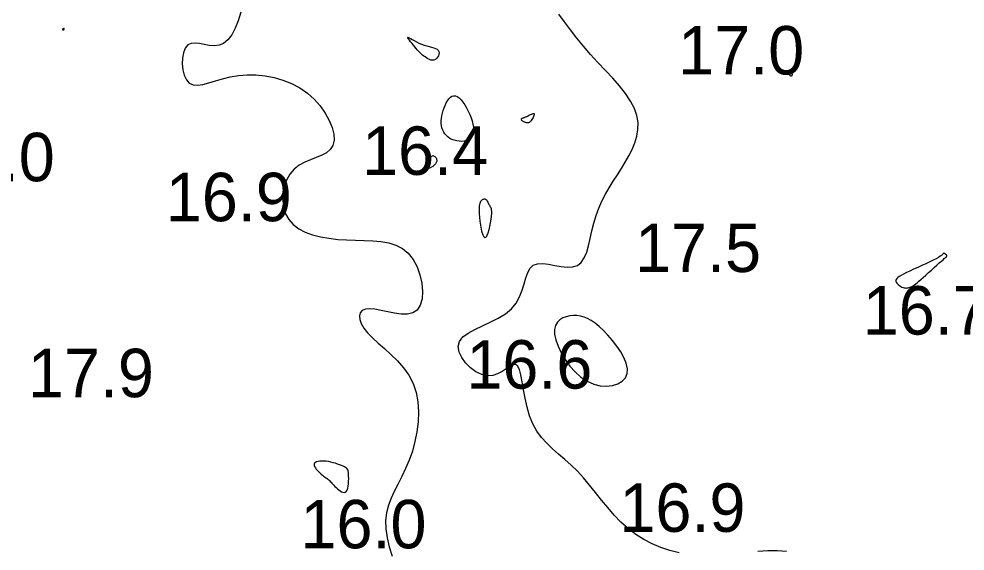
# Model space of a CAD drawing. Extents: x 3040093 to 3056816, y 408076 to 509144.
# Drawn here: x 3045378.4 to 3045476.1, y 433880.3 to 433935.3 of the extents above; entities that cross this region are included whole.
import ezdxf

# ---------------------------------------------------------------- set-up
doc = ezdxf.new("R2010")
doc.units = 0
doc.layers.add('V-CHAN-CONT-EL17', color=7, linetype='Continuous')
doc.layers.add('V-TOPO-SOUN-0610', color=7, linetype='Continuous')

msp = doc.modelspace()

# ---------------------------------------------------------------- linework, layer by layer
at = {"layer": 'V-CHAN-CONT-EL17'}
for points in [[(3045401.338, 433935.95), (3045401.071, 433935.083), (3045400.759, 433934.303), (3045400.404, 433933.637), (3045400.007, 433933.107), (3045399.568, 433932.74), (3045399.09, 433932.546), (3045398.587, 433932.493), (3045398.072, 433932.535), (3045397.562, 433932.627), (3045397.071, 433932.722), (3045396.615, 433932.775), (3045396.208, 433932.74), (3045395.866, 433932.573), (3045395.601, 433932.242), (3045395.416, 433931.776), (3045395.312, 433931.221), (3045395.29, 433930.619), (3045395.349, 433930.017), (3045395.49, 433929.456), (3045395.714, 433928.983), (3045396.021, 433928.642), (3045396.411, 433928.463), (3045396.88, 433928.428), (3045397.424, 433928.504), (3045398.037, 433928.659), (3045398.716, 433928.861), (3045399.454, 433929.079), (3045400.249, 433929.279), (3045401.094, 433929.43), (3045401.984, 433929.504), (3045402.904, 433929.495), (3045403.84, 433929.402), (3045404.776, 433929.222), (3045405.696, 433928.955), (3045406.586, 433928.597), (3045407.43, 433928.149), (3045408.212, 433927.608), (3045408.917, 433926.977), (3045409.536, 433926.279), (3045410.058, 433925.541), (3045410.472, 433924.789), (3045410.768, 433924.052), (3045410.937, 433923.356), (3045410.967, 433922.728), (3045410.85, 433922.196), (3045410.581, 433921.776), (3045410.185, 433921.449), (3045409.691, 433921.184), (3045409.132, 433920.952), (3045408.537, 433920.721), (3045407.938, 433920.463), (3045407.365, 433920.147), (3045406.848, 433919.742), (3045406.415, 433919.228), (3045406.075, 433918.623), (3045405.834, 433917.952), (3045405.696, 433917.242), (3045405.668, 433916.519), (3045405.755, 433915.81), (3045405.961, 433915.142), (3045406.294, 433914.54), (3045406.754, 433914.026), (3045407.329, 433913.597), (3045408.001, 433913.248), (3045408.756, 433912.97), (3045409.576, 433912.757), (3045410.445, 433912.601), (3045411.346, 433912.495), (3045412.264, 433912.431), (3045413.181, 433912.401), (3045414.087, 433912.381), (3045414.97, 433912.346), (3045415.818, 433912.271), (3045416.62, 433912.13), (3045417.364, 433911.898), (3045418.039, 433911.55), (3045418.634, 433911.061), (3045419.138, 433910.417), (3045419.544, 433909.654), (3045419.845, 433908.818), (3045420.035, 433907.956), (3045420.108, 433907.115), (3045420.057, 433906.344), (3045419.876, 433905.688), (3045419.559, 433905.194), (3045419.106, 433904.896), (3045418.542, 433904.767), (3045417.9, 433904.769), (3045417.212, 433904.86), (3045416.51, 433905.001), (3045415.827, 433905.153), (3045415.195, 433905.275), (3045414.645, 433905.327), (3045414.206, 433905.279), (3045413.882, 433905.132), (3045413.676, 433904.899), (3045413.587, 433904.591), (3045413.616, 433904.219), (3045413.765, 433903.795), (3045414.033, 433903.331), (3045414.423, 433902.838), (3045414.928, 433902.324), (3045415.523, 433901.785), (3045416.173, 433901.213), (3045416.848, 433900.602), (3045417.513, 433899.943), (3045418.137, 433899.229), (3045418.687, 433898.453), (3045419.13, 433897.607), (3045419.441, 433896.688), (3045419.625, 433895.711), (3045419.693, 433894.694), (3045419.659, 433893.657), (3045419.533, 433892.617), (3045419.328, 433891.596), (3045419.056, 433890.61), (3045418.729, 433889.679), (3045418.361, 433888.817), (3045417.97, 433888.012), (3045417.577, 433887.247), (3045417.202, 433886.506), (3045416.866, 433885.772), (3045416.589, 433885.029), (3045416.391, 433884.259), (3045416.294, 433883.447), (3045416.311, 433882.579), (3045416.439, 433881.666), (3045416.668, 433880.719), (3045416.988, 433879.752)], [(3045446.621, 433880.118), (3045445.66, 433880.351), (3045444.725, 433880.658), (3045443.821, 433881.038), (3045442.952, 433881.492), (3045442.124, 433882.018), (3045441.341, 433882.618), (3045440.604, 433883.288), (3045439.908, 433884.013), (3045439.243, 433884.777), (3045438.603, 433885.56), (3045437.977, 433886.347), (3045437.357, 433887.118), (3045436.735, 433887.856), (3045436.102, 433888.545), (3045435.453, 433889.172), (3045434.798, 433889.752), (3045434.151, 433890.307), (3045433.524, 433890.857), (3045432.932, 433891.424), (3045432.387, 433892.029), (3045431.903, 433892.693), (3045431.494, 433893.437), (3045431.167, 433894.272), (3045430.912, 433895.166), (3045430.71, 433896.077), (3045430.546, 433896.963), (3045430.402, 433897.782), (3045430.262, 433898.492), (3045430.108, 433899.05), (3045429.924, 433899.416), (3045429.696, 433899.561), (3045429.421, 433899.524), (3045429.1, 433899.356), (3045428.733, 433899.11), (3045428.319, 433898.839), (3045427.861, 433898.594), (3045427.357, 433898.428), (3045426.808, 433898.394), (3045426.221, 433898.531), (3045425.626, 433898.819), (3045425.059, 433899.228), (3045424.556, 433899.724), (3045424.155, 433900.276), (3045423.891, 433900.852), (3045423.8, 433901.419), (3045423.92, 433901.946), (3045424.271, 433902.409), (3045424.817, 433902.82), (3045425.506, 433903.198), (3045426.288, 433903.564), (3045427.109, 433903.938), (3045427.919, 433904.34), (3045428.667, 433904.789), (3045429.3, 433905.307), (3045429.782, 433905.904), (3045430.134, 433906.557), (3045430.393, 433907.233), (3045430.594, 433907.9), (3045430.774, 433908.524), (3045430.968, 433909.075), (3045431.213, 433909.519), (3045431.544, 433909.823), (3045431.987, 433909.969), (3045432.524, 433909.986), (3045433.126, 433909.917), (3045433.765, 433909.806), (3045434.411, 433909.696), (3045435.036, 433909.63), (3045435.611, 433909.651), (3045436.108, 433909.803), (3045436.505, 433910.116), (3045436.815, 433910.576), (3045437.06, 433911.157), (3045437.259, 433911.833), (3045437.435, 433912.577), (3045437.607, 433913.363), (3045437.796, 433914.165), (3045438.024, 433914.956), (3045438.305, 433915.716), (3045438.635, 433916.445), (3045439.003, 433917.148), (3045439.399, 433917.83), (3045439.812, 433918.497), (3045440.231, 433919.155), (3045440.647, 433919.808), (3045441.048, 433920.462), (3045441.424, 433921.122), (3045441.759, 433921.79), (3045442.036, 433922.467), (3045442.24, 433923.154), (3045442.355, 433923.852), (3045442.364, 433924.563), (3045442.251, 433925.288), (3045442, 433926.027), (3045441.602, 433926.783), (3045441.076, 433927.553), (3045440.449, 433928.338), (3045439.747, 433929.136), (3045438.997, 433929.947), (3045438.225, 433930.769), (3045437.457, 433931.601), (3045436.721, 433932.444), (3045436.035, 433933.293), (3045435.393, 433934.137), (3045434.779, 433934.961), (3045434.178, 433935.752)], [(3045457.714, 433880.233), (3045456.746, 433880.302), (3045455.755, 433880.304), (3045454.748, 433880.255)]]:
    msp.add_lwpolyline(points, dxfattribs=at)
for points in [[(3045383.043, 433934.136), (3045383.051, 433934.14), (3045383.059, 433934.144), (3045383.065, 433934.15), (3045383.072, 433934.156), (3045383.078, 433934.164), (3045383.083, 433934.172), (3045383.089, 433934.182), (3045383.094, 433934.193), (3045383.099, 433934.204), (3045383.104, 433934.216), (3045383.108, 433934.227), (3045383.11, 433934.238), (3045383.112, 433934.249), (3045383.111, 433934.258), (3045383.109, 433934.265), (3045383.106, 433934.271), (3045383.1, 433934.274), (3045383.093, 433934.276), (3045383.084, 433934.277), (3045383.075, 433934.276), (3045383.064, 433934.275), (3045383.054, 433934.272), (3045383.043, 433934.269), (3045383.032, 433934.265), (3045383.021, 433934.261), (3045383.01, 433934.257), (3045383, 433934.252), (3045382.99, 433934.248), (3045382.981, 433934.243), (3045382.972, 433934.239), (3045382.965, 433934.235), (3045382.958, 433934.232), (3045382.953, 433934.229), (3045382.948, 433934.226), (3045382.944, 433934.222), (3045382.942, 433934.219), (3045382.939, 433934.215), (3045382.938, 433934.21), (3045382.937, 433934.205), (3045382.937, 433934.198), (3045382.938, 433934.19), (3045382.939, 433934.182), (3045382.942, 433934.174), (3045382.945, 433934.166), (3045382.949, 433934.158), (3045382.954, 433934.151), (3045382.961, 433934.145), (3045382.968, 433934.139), (3045382.977, 433934.135), (3045382.986, 433934.132), (3045382.996, 433934.131), (3045383.006, 433934.13), (3045383.016, 433934.13), (3045383.026, 433934.131), (3045383.035, 433934.133)], [(3045419.324, 433932.373), (3045419.177, 433932.546), (3045419.025, 433932.726), (3045418.881, 433932.902), (3045418.753, 433933.065), (3045418.653, 433933.203), (3045418.591, 433933.306), (3045418.578, 433933.363), (3045418.621, 433933.368), (3045418.716, 433933.326), (3045418.856, 433933.248), (3045419.036, 433933.143), (3045419.247, 433933.022), (3045419.483, 433932.893), (3045419.737, 433932.768), (3045420.003, 433932.655), (3045420.273, 433932.562), (3045420.541, 433932.486), (3045420.8, 433932.42), (3045421.044, 433932.358), (3045421.265, 433932.295), (3045421.457, 433932.223), (3045421.613, 433932.138), (3045421.726, 433932.032), (3045421.793, 433931.903), (3045421.814, 433931.756), (3045421.797, 433931.601), (3045421.744, 433931.447), (3045421.663, 433931.302), (3045421.556, 433931.177), (3045421.43, 433931.079), (3045421.289, 433931.018), (3045421.137, 433931), (3045420.98, 433931.02), (3045420.82, 433931.072), (3045420.662, 433931.146), (3045420.509, 433931.237), (3045420.366, 433931.335), (3045420.235, 433931.435), (3045420.121, 433931.528), (3045420.026, 433931.608), (3045419.945, 433931.68), (3045419.874, 433931.747), (3045419.806, 433931.817), (3045419.736, 433931.893), (3045419.659, 433931.982), (3045419.567, 433932.089), (3045419.457, 433932.218)], [(3045458.164, 433929.374), (3045458.184, 433929.373), (3045458.201, 433929.376), (3045458.216, 433929.384), (3045458.23, 433929.394), (3045458.242, 433929.407), (3045458.254, 433929.421), (3045458.266, 433929.435), (3045458.279, 433929.449), (3045458.291, 433929.463), (3045458.302, 433929.476), (3045458.311, 433929.489), (3045458.318, 433929.503), (3045458.32, 433929.516), (3045458.317, 433929.529), (3045458.309, 433929.543), (3045458.294, 433929.557), (3045458.274, 433929.57), (3045458.249, 433929.584), (3045458.22, 433929.596), (3045458.189, 433929.608), (3045458.156, 433929.617), (3045458.123, 433929.625), (3045458.09, 433929.63), (3045458.058, 433929.632), (3045458.029, 433929.631), (3045458.004, 433929.627), (3045457.982, 433929.62), (3045457.965, 433929.609), (3045457.953, 433929.596), (3045457.949, 433929.579), (3045457.952, 433929.559), (3045457.962, 433929.535), (3045457.98, 433929.51), (3045458.002, 433929.483), (3045458.029, 433929.457), (3045458.057, 433929.433), (3045458.087, 433929.411), (3045458.115, 433929.393), (3045458.142, 433929.38)], [(3045425.062, 433922.91), (3045424.874, 433922.784), (3045424.656, 433922.695), (3045424.415, 433922.64), (3045424.159, 433922.618), (3045423.896, 433922.626), (3045423.635, 433922.663), (3045423.384, 433922.726), (3045423.15, 433922.814), (3045422.935, 433922.925), (3045422.741, 433923.057), (3045422.568, 433923.21), (3045422.418, 433923.382), (3045422.291, 433923.572), (3045422.19, 433923.778), (3045422.115, 433923.999), (3045422.066, 433924.234), (3045422.043, 433924.479), (3045422.044, 433924.734), (3045422.067, 433924.996), (3045422.109, 433925.263), (3045422.17, 433925.532), (3045422.247, 433925.801), (3045422.339, 433926.069), (3045422.443, 433926.331), (3045422.56, 433926.581), (3045422.688, 433926.81), (3045422.828, 433927.008), (3045422.979, 433927.168), (3045423.141, 433927.28), (3045423.313, 433927.337), (3045423.496, 433927.329), (3045423.687, 433927.25), (3045423.885, 433927.107), (3045424.084, 433926.909), (3045424.282, 433926.664), (3045424.475, 433926.382), (3045424.659, 433926.072), (3045424.83, 433925.743), (3045424.985, 433925.403), (3045425.119, 433925.061), (3045425.23, 433924.724), (3045425.314, 433924.395), (3045425.368, 433924.082), (3045425.388, 433923.787), (3045425.37, 433923.518), (3045425.312, 433923.279), (3045425.21, 433923.075)], [(3045430.305, 433924.862), (3045430.307, 433924.892), (3045430.321, 433924.921), (3045430.344, 433924.948), (3045430.374, 433924.974), (3045430.409, 433924.998), (3045430.449, 433925.02), (3045430.491, 433925.04), (3045430.535, 433925.059), (3045430.581, 433925.077), (3045430.63, 433925.096), (3045430.684, 433925.116), (3045430.743, 433925.14), (3045430.81, 433925.168), (3045430.885, 433925.202), (3045430.97, 433925.243), (3045431.064, 433925.292), (3045431.165, 433925.344), (3045431.267, 433925.396), (3045431.366, 433925.442), (3045431.457, 433925.478), (3045431.536, 433925.5), (3045431.597, 433925.503), (3045431.636, 433925.482), (3045431.65, 433925.435), (3045431.641, 433925.365), (3045431.613, 433925.278), (3045431.571, 433925.179), (3045431.519, 433925.075), (3045431.46, 433924.971), (3045431.398, 433924.873), (3045431.338, 433924.786), (3045431.283, 433924.714), (3045431.233, 433924.657), (3045431.187, 433924.614), (3045431.144, 433924.581), (3045431.105, 433924.559), (3045431.068, 433924.544), (3045431.033, 433924.534), (3045430.999, 433924.529), (3045430.965, 433924.526), (3045430.931, 433924.526), (3045430.896, 433924.529), (3045430.86, 433924.534), (3045430.821, 433924.542), (3045430.779, 433924.554), (3045430.734, 433924.569), (3045430.685, 433924.589), (3045430.631, 433924.612), (3045430.574, 433924.638), (3045430.518, 433924.667), (3045430.463, 433924.698), (3045430.413, 433924.731), (3045430.37, 433924.764), (3045430.336, 433924.798), (3045430.314, 433924.83)], [(3045420.635, 433920.099), (3045420.643, 433920.14), (3045420.656, 433920.184), (3045420.672, 433920.232), (3045420.692, 433920.285), (3045420.716, 433920.346), (3045420.742, 433920.416), (3045420.77, 433920.495), (3045420.801, 433920.586), (3045420.835, 433920.683), (3045420.872, 433920.782), (3045420.912, 433920.878), (3045420.957, 433920.967), (3045421.006, 433921.042), (3045421.06, 433921.1), (3045421.12, 433921.135), (3045421.185, 433921.145), (3045421.253, 433921.13), (3045421.321, 433921.095), (3045421.387, 433921.043), (3045421.447, 433920.978), (3045421.499, 433920.904), (3045421.54, 433920.824), (3045421.566, 433920.741), (3045421.577, 433920.659), (3045421.572, 433920.579), (3045421.554, 433920.501), (3045421.524, 433920.425), (3045421.483, 433920.351), (3045421.434, 433920.28), (3045421.378, 433920.213), (3045421.316, 433920.149), (3045421.25, 433920.089), (3045421.181, 433920.033), (3045421.112, 433919.983), (3045421.043, 433919.94), (3045420.976, 433919.904), (3045420.913, 433919.876), (3045420.854, 433919.858), (3045420.802, 433919.85), (3045420.758, 433919.852), (3045420.72, 433919.865), (3045420.69, 433919.885), (3045420.666, 433919.912), (3045420.649, 433919.945), (3045420.638, 433919.981), (3045420.632, 433920.02), (3045420.631, 433920.06)], [(3045425.981, 433915.452), (3045425.979, 433915.711), (3045425.99, 433915.924), (3045426.012, 433916.096), (3045426.044, 433916.232), (3045426.085, 433916.341), (3045426.132, 433916.427), (3045426.184, 433916.496), (3045426.24, 433916.555), (3045426.298, 433916.602), (3045426.358, 433916.638), (3045426.418, 433916.661), (3045426.479, 433916.671), (3045426.538, 433916.668), (3045426.595, 433916.649), (3045426.65, 433916.614), (3045426.701, 433916.564), (3045426.748, 433916.5), (3045426.794, 433916.426), (3045426.838, 433916.345), (3045426.881, 433916.26), (3045426.923, 433916.174), (3045426.967, 433916.09), (3045427.011, 433916.012), (3045427.058, 433915.94), (3045427.103, 433915.867), (3045427.145, 433915.784), (3045427.18, 433915.683), (3045427.206, 433915.554), (3045427.22, 433915.387), (3045427.219, 433915.174), (3045427.201, 433914.905), (3045427.162, 433914.578), (3045427.106, 433914.212), (3045427.035, 433913.834), (3045426.953, 433913.468), (3045426.861, 433913.141), (3045426.763, 433912.879), (3045426.663, 433912.707), (3045426.562, 433912.651), (3045426.464, 433912.729), (3045426.371, 433912.924), (3045426.283, 433913.211), (3045426.204, 433913.564), (3045426.134, 433913.959), (3045426.075, 433914.37), (3045426.029, 433914.771), (3045425.997, 433915.139)], [(3045469.034, 433908.079), (3045469.093, 433907.982), (3045469.173, 433907.887), (3045469.27, 433907.796), (3045469.379, 433907.711), (3045469.497, 433907.635), (3045469.618, 433907.572), (3045469.739, 433907.522), (3045469.855, 433907.489), (3045469.966, 433907.471), (3045470.073, 433907.467), (3045470.175, 433907.474), (3045470.273, 433907.492), (3045470.368, 433907.517), (3045470.458, 433907.548), (3045470.546, 433907.585), (3045470.63, 433907.625), (3045470.717, 433907.672), (3045470.811, 433907.73), (3045470.918, 433907.804), (3045471.042, 433907.898), (3045471.188, 433908.016), (3045471.363, 433908.163), (3045471.571, 433908.343), (3045471.815, 433908.557), (3045472.086, 433908.799), (3045472.374, 433909.057), (3045472.668, 433909.322), (3045472.958, 433909.584), (3045473.233, 433909.832), (3045473.481, 433910.056), (3045473.693, 433910.247), (3045473.861, 433910.396), (3045473.987, 433910.507), (3045474.078, 433910.586), (3045474.14, 433910.639), (3045474.179, 433910.67), (3045474.201, 433910.687), (3045474.212, 433910.695), (3045474.218, 433910.699), (3045474.224, 433910.705), (3045474.231, 433910.713), (3045474.239, 433910.723), (3045474.247, 433910.734), (3045474.254, 433910.745), (3045474.26, 433910.758), (3045474.265, 433910.771), (3045474.268, 433910.783), (3045474.269, 433910.795), (3045474.268, 433910.806), (3045474.263, 433910.818), (3045474.256, 433910.832), (3045474.245, 433910.846), (3045474.23, 433910.863), (3045474.21, 433910.883), (3045474.186, 433910.906), (3045474.158, 433910.932), (3045474.126, 433910.961), (3045474.092, 433910.989), (3045474.057, 433911.015), (3045474.022, 433911.037), (3045473.99, 433911.053), (3045473.96, 433911.061), (3045473.936, 433911.058), (3045473.915, 433911.044), (3045473.891, 433911.017), (3045473.855, 433910.975), (3045473.796, 433910.916), (3045473.706, 433910.841), (3045473.575, 433910.747), (3045473.393, 433910.633), (3045473.152, 433910.497), (3045472.846, 433910.34), (3045472.487, 433910.166), (3045472.089, 433909.98), (3045471.67, 433909.787), (3045471.245, 433909.593), (3045470.828, 433909.402), (3045470.437, 433909.221), (3045470.086, 433909.055), (3045469.788, 433908.906), (3045469.543, 433908.775), (3045469.348, 433908.657), (3045469.199, 433908.551), (3045469.093, 433908.452), (3045469.026, 433908.358), (3045468.997, 433908.267), (3045469, 433908.174)], [(3045437.784, 433897.539), (3045438.462, 433897.374), (3045439.12, 433897.331), (3045439.733, 433897.4), (3045440.278, 433897.574), (3045440.728, 433897.843), (3045441.058, 433898.198), (3045441.243, 433898.632), (3045441.268, 433899.134), (3045441.147, 433899.688), (3045440.907, 433900.275), (3045440.572, 433900.877), (3045440.167, 433901.477), (3045439.717, 433902.055), (3045439.248, 433902.594), (3045438.783, 433903.076), (3045438.344, 433903.486), (3045437.929, 433903.825), (3045437.534, 433904.097), (3045437.155, 433904.308), (3045436.785, 433904.461), (3045436.421, 433904.561), (3045436.056, 433904.612), (3045435.687, 433904.62), (3045435.311, 433904.587), (3045434.941, 433904.507), (3045434.594, 433904.375), (3045434.284, 433904.183), (3045434.03, 433903.924), (3045433.845, 433903.593), (3045433.748, 433903.182), (3045433.753, 433902.685), (3045433.873, 433902.101), (3045434.1, 433901.452), (3045434.424, 433900.768), (3045434.834, 433900.078), (3045435.319, 433899.411), (3045435.868, 433898.795), (3045436.469, 433898.259), (3045437.112, 433897.833)], [(3045409.77, 433888.127), (3045409.881, 433888.044), (3045409.984, 433887.971), (3045410.081, 433887.906), (3045410.171, 433887.846), (3045410.257, 433887.786), (3045410.34, 433887.724), (3045410.421, 433887.656), (3045410.501, 433887.58), (3045410.583, 433887.496), (3045410.666, 433887.403), (3045410.754, 433887.304), (3045410.847, 433887.199), (3045410.948, 433887.088), (3045411.057, 433886.972), (3045411.178, 433886.852), (3045411.309, 433886.73), (3045411.449, 433886.612), (3045411.593, 433886.507), (3045411.736, 433886.423), (3045411.876, 433886.368), (3045412.007, 433886.351), (3045412.126, 433886.378), (3045412.228, 433886.459), (3045412.311, 433886.598), (3045412.376, 433886.786), (3045412.423, 433887.011), (3045412.455, 433887.259), (3045412.473, 433887.518), (3045412.48, 433887.777), (3045412.477, 433888.021), (3045412.465, 433888.239), (3045412.446, 433888.421), (3045412.418, 433888.569), (3045412.378, 433888.69), (3045412.324, 433888.788), (3045412.252, 433888.87), (3045412.16, 433888.941), (3045412.045, 433889.006), (3045411.905, 433889.071), (3045411.738, 433889.141), (3045411.547, 433889.213), (3045411.337, 433889.287), (3045411.112, 433889.357), (3045410.876, 433889.423), (3045410.635, 433889.481), (3045410.392, 433889.529), (3045410.153, 433889.564), (3045409.92, 433889.583), (3045409.7, 433889.587), (3045409.497, 433889.575), (3045409.317, 433889.546), (3045409.164, 433889.5), (3045409.042, 433889.438), (3045408.958, 433889.358), (3045408.916, 433889.261), (3045408.919, 433889.147), (3045408.961, 433889.02), (3045409.037, 433888.884), (3045409.137, 433888.743), (3045409.256, 433888.603), (3045409.386, 433888.466), (3045409.519, 433888.339), (3045409.649, 433888.225)]]:
    msp.add_lwpolyline(points, close=True, dxfattribs=at)

# ---------------------------------------------------------------- texts
at = {"layer": 'V-TOPO-SOUN-0610'}
for s, p in [('17.0 ', (3045446.513, 433929.53)), ('16.4 ', (3045413.863, 433919.16)), ('17.0 ', (3045369.113, 433918.5)), ('16.9 ', (3045393.593, 433914.37)), ('17.5 ', (3045442.053, 433909.12)), ('16.7 ', (3045465.573, 433902.66)), ('16.6 ', (3045424.633, 433897.08)), ('17.9 ', (3045379.353, 433896.19)), ('16.9 ', (3045440.443, 433882.28)), ('16.0 ', (3045407.503, 433880.58))]:
    msp.add_text(s, height=5, dxfattribs=at).set_placement(p)

doc.saveas('drawing.dxf')
